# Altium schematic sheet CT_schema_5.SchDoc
size 218 x 198 mm
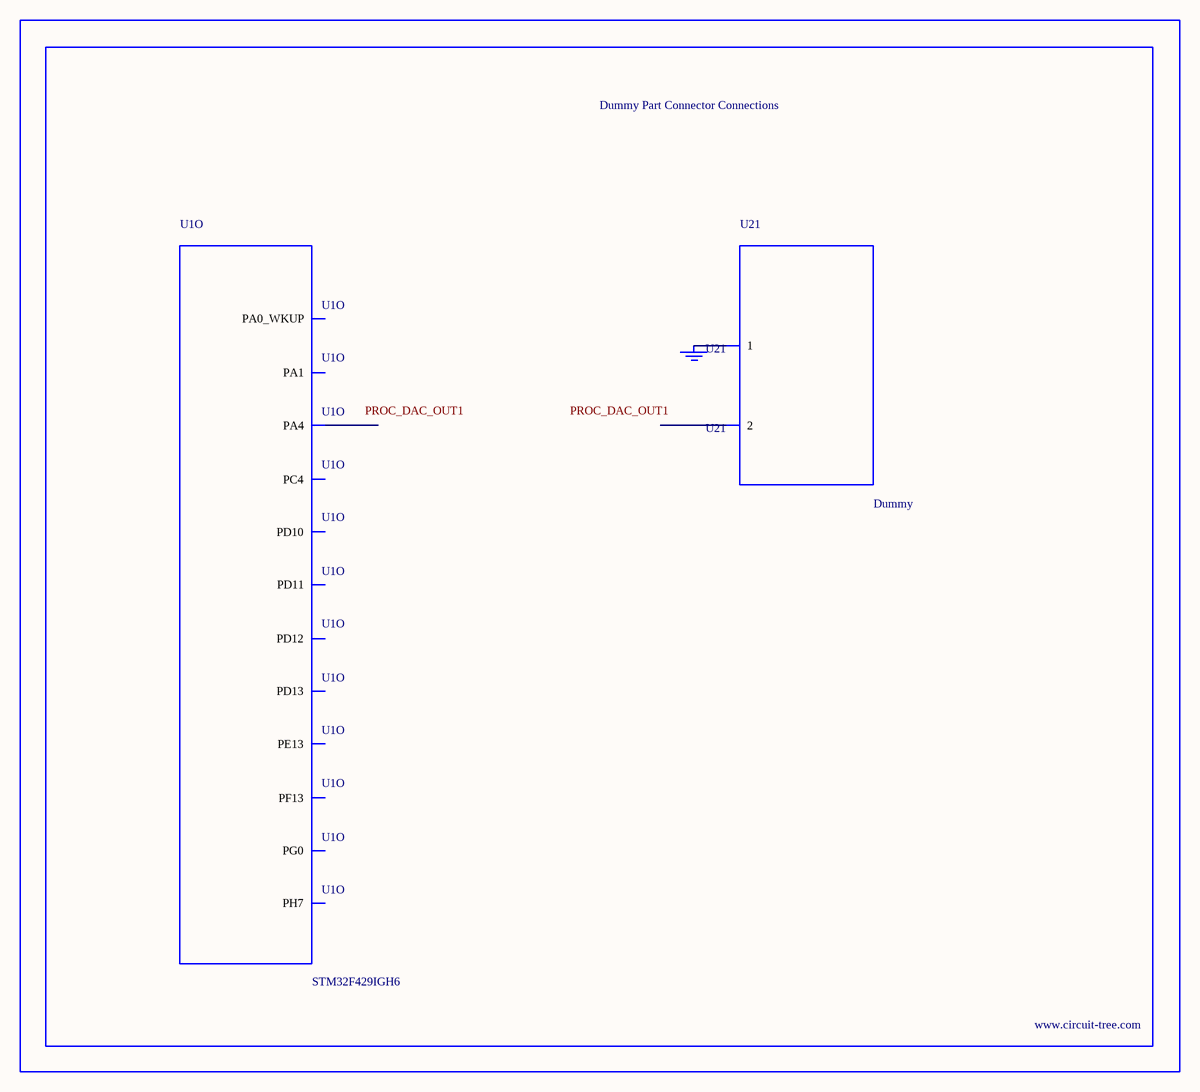
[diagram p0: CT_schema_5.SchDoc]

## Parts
BORDER4  (no value)
GND_INSTANCE_4_0  (no value)
U1  STM32F429IGH6  [UFBGA176_25]  (part O of 15)
U21  Dummy  [DUMMY_PACKAGE_252]

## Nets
NetGND_INSTANCE_4_0_0: GND_INSTANCE_4_0.0(GND) U21.1

Not connected (* = marked no-connect by the designer): U1 M15(PD13) N2(PA1) N3(PA0_WKUP) N4(PA4) N5(PC4) N6(PF13) N7(PG0) N11(PE13) N12(PH7) N13(PD12) N14(PD11) N15(PD10); U21 2

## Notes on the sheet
- Labels drawn without touching a wire or pin: PROC_DAC_OUT1

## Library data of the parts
BORDER4 = BORDER_PAGE4
GND_INSTANCE_4_0 = GND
